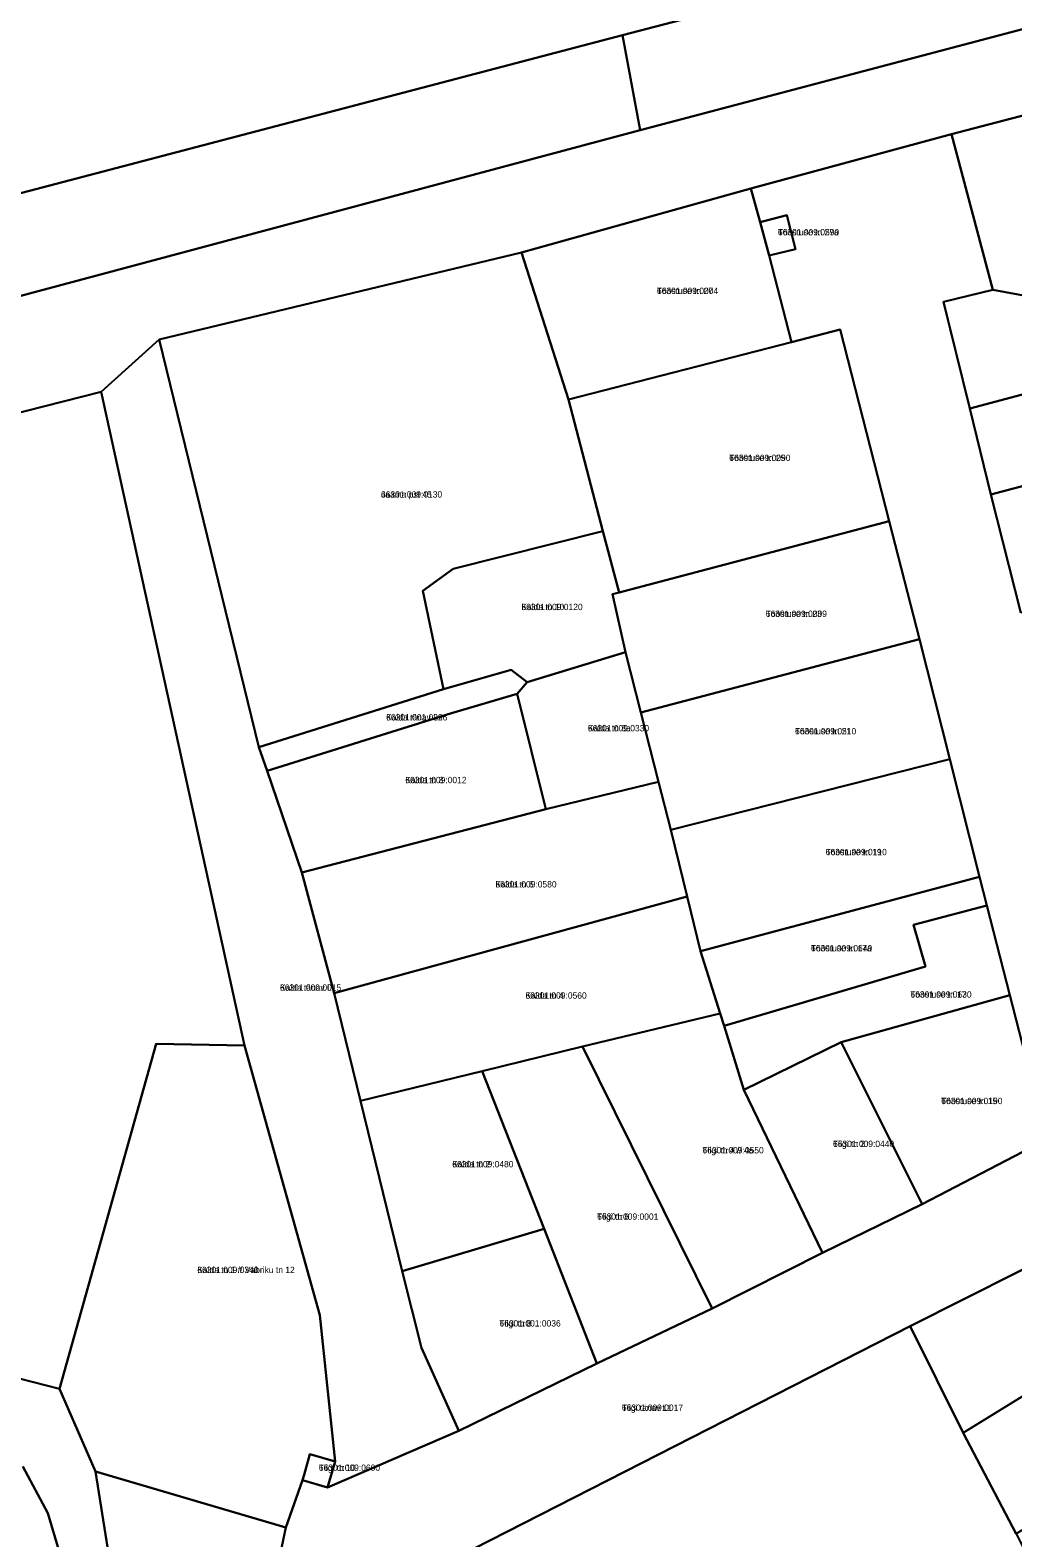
# Model space of a CAD drawing. Extents: x 632278 to 636344, y 6578401 to 6583362.
# Drawn here: x 633717.6 to 633950.5, y 6581799.1 to 6582156.3 of the extents above; entities that cross this region are included whole.
import ezdxf

# ---------------------------------------------------------------- set-up
doc = ezdxf.new("R2010")
doc.units = 0
for name, color, linetype in [('L_AADRESS', 7, 'Continuous'), ('PIIR', 7, 'Continuous'), ('TUNNUS', 7, 'Continuous')]:
    doc.layers.add(name, color=color, linetype=linetype)

msp = doc.modelspace()

# ---------------------------------------------------------------- linework, layer by layer
at = {"layer": 'PIIR'}
for points in [[(634262.64, 6582266.01), (634217.69, 6582254.21), (634219.45, 6582247.65), (634212.21, 6582245.86), (634195.12, 6582241.6), (634176.42, 6582237.01), (634173.96, 6582236.4), (634090.38, 6582215.74), (634039.58, 6582202.46), (633961.3, 6582182.01), (633857.97, 6582155.11), (633730.08, 6582121.51), (633462.58, 6582051.42)], [(633468.65, 6582027.37), (633862.14, 6582132.61), (633966.83, 6582160.24), (634045.32, 6582180.97), (634095.76, 6582194.28), (634171.8, 6582213.35), (634184.13, 6582216.44), (634190.63, 6582199.04), (634142.64, 6582185.7), (634076.76, 6582167.38), (634032.67, 6582155.81), (634021.59, 6582153.91), (633984.06, 6582144.17), (633935.96, 6582131.59), (633888.34, 6582118.77), (633834.04, 6582103.56), (633748.13, 6582082.98), (633734.4, 6582070.6), (633580.94, 6582031.55)], [(633957.19, 6581898.78), (633949.71, 6581927.69), (633944.29, 6581948.94), (633942.58, 6581955.67), (633935.55, 6581983.54), (633928.35, 6582012.03), (633921.19, 6582039.93), (633909.57, 6582085.37), (633898, 6582082.38), (633892.71, 6582102.89), (633898.97, 6582104.36), (633896.91, 6582112.48), (633890.6, 6582110.8), (633888.34, 6582118.77), (633935.96, 6582131.59), (633945.69, 6582094.79), (633934.01, 6582091.91), (633935.04, 6582087.7), (633940.23, 6582066.68), (633945.26, 6582046.29), (633952.38, 6582018.2)], [(633676.34, 6581846.74), (633724.51, 6581834.37), (633733.08, 6581814.8), (633738.36, 6581781.52)], [(633715.84, 6581815.99), (633721.74, 6581804.98), (633726.32, 6581789.56), (633732.5, 6581765.33), (633739.89, 6581723.53), (633746.48, 6581689.57), (633757.6, 6581637.04), (633765.24, 6581606.48), (633775.45, 6581573.33), (633785.63, 6581544.01), (633789.72, 6581534.39), (633794.98, 6581524.63), (633816.52, 6581488.37), (633779.15, 6581461.79), (633770.88, 6581488.48), (633758.48, 6581488.79), (633737.73, 6581482.83), (633725.88, 6581526.24), (633654.22, 6581502.95)], [(633726.32, 6581789.56), (633721.74, 6581804.98), (633715.84, 6581815.99)]]:
    msp.add_lwpolyline(points, dxfattribs=at)
for points in [[(633961.3, 6582182.01), (633966.83, 6582160.24), (633862.14, 6582132.61), (633857.97, 6582155.11)], [(633468.65, 6582027.37), (633117.3, 6581933.19), (633092.94, 6581927.34), (633069.22, 6581920.67), (633045.02, 6581914.19), (633045.28, 6581913.19), (633021.21, 6581906.88), (632996.93, 6581900.69), (632973.03, 6581894.3), (632949.09, 6581888.13), (632929.99, 6581882.98), (632922.41, 6581910.15), (633111.38, 6581959.61), (633249.26, 6581995.68), (633462.58, 6582051.42), (633730.08, 6582121.51), (633857.97, 6582155.11), (633862.14, 6582132.61)], [(633984.06, 6582144.17), (633989.26, 6582123.94), (633990.45, 6582119.57), (633998.8, 6582090.29), (633986.84, 6582087.18), (633945.69, 6582094.79), (633935.96, 6582131.59)], [(633888.34, 6582118.77), (633890.6, 6582110.8), (633892.71, 6582102.89), (633898, 6582082.38), (633845.19, 6582068.75), (633834.04, 6582103.56)], [(633896.91, 6582112.48), (633898.97, 6582104.36), (633892.71, 6582102.89), (633890.6, 6582110.8)], [(633748.13, 6582082.98), (633834.04, 6582103.56), (633845.19, 6582068.75), (633853.31, 6582037.62), (633817.82, 6582028.68), (633810.66, 6582023.45), (633815.5, 6582000.14), (633771.76, 6581986.42)], [(633934.01, 6582091.91), (633945.69, 6582094.79), (633986.84, 6582087.18), (633988.91, 6582079.57), (633940.23, 6582066.68)], [(633857.18, 6582023.03), (633853.31, 6582037.62), (633845.19, 6582068.75), (633898, 6582082.38), (633909.57, 6582085.37), (633921.19, 6582039.93)], [(633734.4, 6582070.6), (633748.13, 6582082.98), (633771.76, 6581986.42), (633773.74, 6581980.78), (633781.94, 6581956.71), (633789.59, 6581928.17), (633795.83, 6581902.61), (633805.72, 6581862.29), (633810.3, 6581844.15), (633819.19, 6581824.49), (633788.02, 6581811.01), (633789.89, 6581817.21), (633786.23, 6581851.82), (633768.37, 6581915.77)], [(633945.26, 6582046.29), (633940.23, 6582066.68), (633988.91, 6582079.57), (633994.43, 6582059.31)], [(633580.94, 6582031.55), (633734.4, 6582070.6), (633768.37, 6581915.77), (633747.48, 6581916.12), (633724.51, 6581834.37), (633676.34, 6581846.74), (633659.91, 6581850.73), (633624.16, 6581859.21), (633613.99, 6581908.56), (633613.38, 6581912.42), (633592.88, 6581987.35)], [(633952.38, 6582018.2), (633945.26, 6582046.29), (633994.43, 6582059.31), (634001.45, 6582031.02), (633967.32, 6582022.1)], [(633855.57, 6582022.66), (633857.18, 6582023.03), (633921.19, 6582039.93), (633928.35, 6582012.03), (633862.31, 6581994.6), (633858.67, 6582008.88)], [(633815.5, 6582000.14), (633810.66, 6582023.45), (633817.82, 6582028.68), (633853.31, 6582037.62), (633857.18, 6582023.03), (633855.57, 6582022.66), (633858.67, 6582008.88), (633835.33, 6582001.85), (633831.57, 6582004.7)], [(633866.49, 6581978.18), (633862.31, 6581994.6), (633928.35, 6582012.03), (633935.55, 6581983.54), (633869.44, 6581966.85)], [(633833.02, 6581999.04), (633835.33, 6582001.85), (633858.67, 6582008.88), (633862.31, 6581994.6), (633866.49, 6581978.18), (633839.77, 6581971.69)], [(633771.76, 6581986.42), (633815.5, 6582000.14), (633831.57, 6582004.7), (633835.33, 6582001.85), (633833.02, 6581999.04), (633817.45, 6581994.45), (633773.74, 6581980.78)], [(633773.74, 6581980.78), (633817.45, 6581994.45), (633833.02, 6581999.04), (633839.77, 6581971.69), (633781.94, 6581956.71)], [(633935.55, 6581983.54), (633942.58, 6581955.67), (633876.48, 6581938.1), (633873.3, 6581951.07), (633869.44, 6581966.85)], [(633781.94, 6581956.71), (633839.77, 6581971.69), (633866.49, 6581978.18), (633869.44, 6581966.85), (633873.3, 6581951.07), (633789.59, 6581928.17)], [(633881.13, 6581923.33), (633876.48, 6581938.1), (633942.58, 6581955.67), (633944.29, 6581948.94), (633926.95, 6581944.36), (633929.75, 6581934.44), (633882.05, 6581920.38)], [(633795.83, 6581902.61), (633789.59, 6581928.17), (633873.3, 6581951.07), (633876.48, 6581938.1), (633881.13, 6581923.33), (633848.47, 6581915.51), (633824.73, 6581909.66)], [(633886.73, 6581905.24), (633882.05, 6581920.38), (633929.75, 6581934.44), (633926.95, 6581944.36), (633944.29, 6581948.94), (633949.71, 6581927.69), (633909.81, 6581916.52)], [(633949.71, 6581927.69), (633957.19, 6581898.78), (633952.86, 6581890.56), (633928.96, 6581878.19), (633909.81, 6581916.52)], [(633848.47, 6581915.51), (633881.13, 6581923.33), (633882.05, 6581920.38), (633886.73, 6581905.24), (633905.37, 6581866.61), (633879.17, 6581853.47)], [(633724.51, 6581834.37), (633747.48, 6581916.12), (633768.37, 6581915.77), (633786.23, 6581851.82), (633789.89, 6581817.21), (633783.9, 6581818.91), (633782.51, 6581814), (633782.1, 6581812.81), (633778.15, 6581801.53), (633733.08, 6581814.8)], [(633824.73, 6581909.66), (633848.47, 6581915.51), (633879.17, 6581853.47), (633851.9, 6581840.4), (633839.41, 6581872.32)], [(633886.73, 6581905.24), (633909.81, 6581916.52), (633928.96, 6581878.19), (633905.37, 6581866.61)], [(633795.83, 6581902.61), (633824.73, 6581909.66), (633839.41, 6581872.32), (633805.72, 6581862.29)], [(633746.05, 6581778.31), (633776.36, 6581792.95), (633778.15, 6581801.53), (633782.1, 6581812.81), (633788.02, 6581811.01), (633819.19, 6581824.49), (633851.9, 6581840.4), (633879.17, 6581853.47), (633905.37, 6581866.61), (633928.96, 6581878.19), (633952.86, 6581890.56), (633957.19, 6581898.78), (633964.41, 6581868.52), (633926.12, 6581849.23), (633822.63, 6581796.54), (633804.8, 6581787.45), (633771.82, 6581771.23), (633752.6, 6581762.41), (633751.15, 6581759.6)], [(633810.3, 6581844.15), (633805.72, 6581862.29), (633839.41, 6581872.32), (633851.9, 6581840.4), (633819.19, 6581824.49)], [(633926.12, 6581849.23), (633964.41, 6581868.52), (633977.8, 6581847.2), (633957.17, 6581835.32), (633938.65, 6581823.98)], [(633822.63, 6581796.54), (633926.12, 6581849.23), (633938.65, 6581823.98), (633951.22, 6581800.08), (633963.84, 6581775.08), (633962.93, 6581774.45), (633946.33, 6581763.28), (633949.27, 6581756.32), (633921.58, 6581741.86), (633930.19, 6581700.67), (633902.7, 6581686.51)], [(633989.41, 6581828.7), (633991.52, 6581825.32), (633951.22, 6581800.08), (633938.65, 6581823.98), (633957.17, 6581835.32), (633977.8, 6581847.2)], [(633782.51, 6581814), (633783.9, 6581818.91), (633789.89, 6581817.21), (633788.02, 6581811.01), (633782.1, 6581812.81)], [(633738.36, 6581781.52), (633733.08, 6581814.8), (633778.15, 6581801.53), (633776.36, 6581792.95), (633746.05, 6581778.31)]]:
    msp.add_lwpolyline(points, close=True, dxfattribs=at)

# ---------------------------------------------------------------- texts
at = {"layer": 'L_AADRESS'}
for s, p in [('Tööstuse tn 27a', (633894.79, 6582107.65)), ('Tööstuse tn 27', (633866.12, 6582093.76)), ('Tööstuse tn 25', (633883.26, 6582054.2)), ('Jaama pst 45', (633800.72, 6582045.54)), ('Kalda tn 10', (633834.01, 6582018.88)), ('Tööstuse tn 23', (633891.9, 6582017.27)), ('Kalda tänav L2', (633801.95, 6581992.74)), ('Kalda tn 8a', (633849.76, 6581990.16)), ('Tööstuse tn 21', (633898.84, 6581989.44)), ('Kalda tn 8', (633806.49, 6581977.88)), ('Tööstuse tn 19', (633906.1, 6581960.82)), ('Kalda tn 6', (633827.84, 6581953.18)), ('Tööstuse tn 17a', (633902.62, 6581938.03)), ('Kalda tänav L1', (633776.79, 6581928.71)), ('Kalda tn 4', (633834.97, 6581926.84)), ('Tööstuse tn 17', (633926.19, 6581927.09)), ('Tööstuse tn 15', (633933.5, 6581901.85)), ('Tiigi tn 2', (633907.84, 6581891.69)), ('Kalda tn 2', (633817.62, 6581886.88)), ('Tiigi tn 4 // 4a', (633876.92, 6581890.17)), ('Tiigi tn 6', (633851.95, 6581874.45)), ('Kalda tn 1 // Vabriku tn 12', (633757.2, 6581861.83)), ('Tiigi tn 8', (633828.81, 6581849.17)), ('Tiigi tänav L1', (633857.81, 6581829.19)), ('Tiigi tn 10', (633786, 6581814.97))]:
    msp.add_text(s, height=1.5, dxfattribs=at).set_placement(p)
at = {"layer": 'TUNNUS'}
for s, p in [('66301:009:0590', (633894.79, 6582107.65)), ('66301:009:0004', (633866.12, 6582093.76)), ('66301:009:0090', (633883.26, 6582054.2)), ('66301:009:0130', (633800.72, 6582045.54)), ('66301:009:0120', (633834.01, 6582018.88)), ('66301:009:0009', (633891.9, 6582017.27)), ('66301:001:0396', (633801.95, 6581992.74)), ('66301:009:0330', (633849.76, 6581990.16)), ('66301:009:0510', (633898.84, 6581989.44)), ('66301:009:0012', (633806.49, 6581977.88)), ('66301:009:0110', (633906.1, 6581960.82)), ('66301:009:0580', (633827.84, 6581953.18)), ('66301:009:0640', (633902.62, 6581938.03)), ('66301:009:0015', (633776.79, 6581928.71)), ('66301:009:0560', (633834.97, 6581926.84)), ('66301:009:0630', (633926.19, 6581927.09)), ('66301:009:0190', (633933.5, 6581901.85)), ('66301:009:0440', (633907.84, 6581891.69)), ('66301:009:0480', (633817.62, 6581886.88)), ('66301:009:0550', (633876.92, 6581890.17)), ('66301:009:0001', (633851.95, 6581874.45)), ('66301:009:0340', (633757.2, 6581861.83)), ('66301:001:0036', (633828.81, 6581849.17)), ('66301:009:0017', (633857.81, 6581829.19)), ('66301:009:0600', (633786, 6581814.97))]:
    msp.add_text(s, height=1.5, dxfattribs=at).set_placement(p)

doc.saveas('drawing.dxf')
